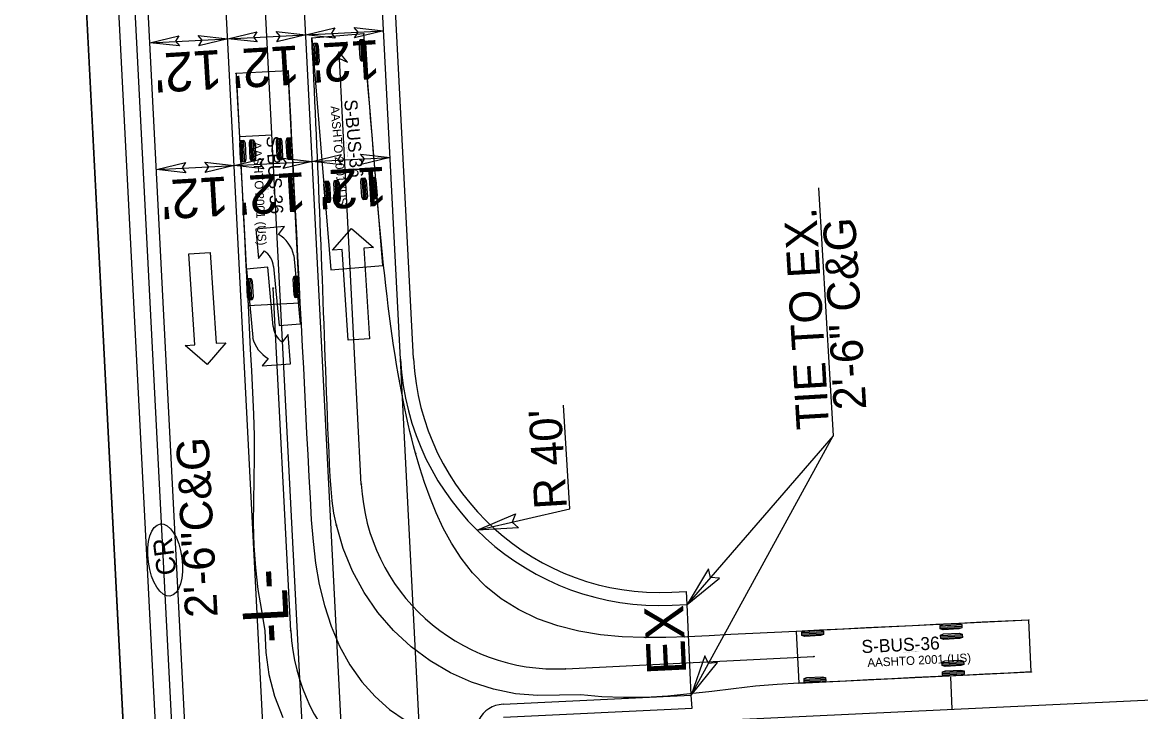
# Model space of a CAD drawing. Extents: x 2367848 to 2369479, y 800728 to 808616.
# Drawn here: x 2368873.3 to 2369045.3, y 802141.1 to 802247.2 of the extents above; entities that cross this region are included whole.
import ezdxf

# ---------------------------------------------------------------- set-up
doc = ezdxf.new("R2010")
doc.units = 0
for name, color, linetype in [('Prop AutoTurn Projected Path', 7, 'Continuous'), ('Prop AutoTurn Simulation', 7, 'Continuous'), ('Prop Conc 2ft 6in Curb and Gutter', 7, 'Continuous'), ('Prop Conc 4in Sidewalk', 7, 'Continuous'), ('Prop Dimension', 7, 'Continuous'), ('Prop EOT', 7, 'Continuous'), ('Prop Horizontal Alignment', 7, 'Continuous'), ('Prop Horizontal Alignment Station Label', 7, 'Continuous'), ('Prop Horizontal Alignment Tick Small', 7, 'Continuous'), ('Prop Lane Arrow CELL', 7, 'Continuous'), ('Prop Lane Lines', 7, 'Continuous'), ('Prop Shade Light', 7, 'Continuous'), ('Prop Terminator CELL', 7, 'Continuous'), ('Prop WCC CELL', 7, 'Continuous'), ('Prop WCR CELL', 7, 'Continuous')]:
    doc.layers.add(name, color=color, linetype=linetype)

# ---------------------------------------------------------------- blocks, each defined once
blk = doc.blocks.new('CR')
at = {"layer": 'Prop WCC CELL'}
blk.add_ellipse((0.02, -0.02), major_axis=(5.61, 0), ratio=0.462467, dxfattribs=at)
blk.add_text('CR', height=3, dxfattribs=at).set_placement((-2.34, -1.5))

msp = doc.modelspace()

# ---------------------------------------------------------------- linework, layer by layer
at = {"layer": 'Prop AutoTurn Projected Path'}
for p, q in [((2368925.4, 802176.14), (2368921.99, 802242.64)), ((2368914.55, 802153.56), (2368911.84, 802206.31)), ((2368956.83, 802147.72), (2368995, 802149.59))]:
    msp.add_line(p, q, dxfattribs=at)
for centre, end in [((2368955.36, 802177.68), 272.8044), ((2368944.51, 802155.1), 272.8888)]:
    msp.add_arc(centre, 30, 182.9405, end, dxfattribs=at)
at = {"layer": 'Prop AutoTurn Simulation'}
for p, q in [((2368925.77, 802245.46), (2368917.8, 802244.8)), ((2368917.8, 802244.8), (2368920.73, 802209.12)), ((2368917.8, 802244.8), (2368917.8, 802244.8)), ((2368925.68, 802244.59), (2368925.85, 802241.26)), ((2368928.71, 802209.78), (2368925.77, 802245.46)), ((2368918.12, 802244.01), (2368918.29, 802240.68)), ((2368918.33, 802244.02), (2368918.5, 802240.69)), ((2368918.54, 802244.03), (2368918.71, 802240.7)), ((2368925.27, 802244.57), (2368925.44, 802241.24)), ((2368925.48, 802244.58), (2368925.65, 802241.25)), ((2368914.13, 802239.77), (2368906.14, 802239.36)), ((2368915.96, 802204.02), (2368914.13, 802239.77)), ((2368906.14, 802239.36), (2368907.97, 802203.61)), ((2368908.54, 802225.8), (2368908.37, 802229.13)), ((2368908.75, 802225.81), (2368908.58, 802229.14)), ((2368908.96, 802225.82), (2368908.79, 802229.15)), ((2368912.7, 802226.02), (2368912.53, 802229.34)), ((2368912.91, 802226.03), (2368912.74, 802229.36)), ((2368913.12, 802226.04), (2368912.95, 802229.37)), ((2368914.2, 802226.09), (2368914.03, 802229.42)), ((2368914.41, 802226.1), (2368914.24, 802229.43)), ((2368914.62, 802226.11), (2368914.45, 802229.44)), ((2368907.04, 802225.72), (2368906.87, 802229.05)), ((2368907.25, 802225.74), (2368907.08, 802229.06)), ((2368907.46, 802225.75), (2368907.29, 802229.08)), ((2368919.82, 802222.76), (2368920.09, 802219.44)), ((2368920.03, 802222.77), (2368920.3, 802219.45)), ((2368920.24, 802222.79), (2368920.51, 802219.47)), ((2368921.32, 802222.88), (2368921.59, 802219.56)), ((2368921.52, 802222.9), (2368921.8, 802219.58)), ((2368921.73, 802222.92), (2368922, 802219.59)), ((2368925.47, 802223.22), (2368925.74, 802219.9)), ((2368925.68, 802223.24), (2368925.95, 802219.92)), ((2368925.88, 802223.26), (2368926.16, 802219.93)), ((2368926.96, 802223.35), (2368927.24, 802220.02)), ((2368927.17, 802223.36), (2368927.44, 802220.04)), ((2368927.38, 802223.38), (2368927.65, 802220.06)), ((2368920.73, 802209.12), (2368928.71, 802209.78)), ((2368908.14, 802204.45), (2368907.97, 802207.78)), ((2368908.35, 802204.46), (2368908.17, 802207.79)), ((2368908.55, 802204.47), (2368908.38, 802207.8)), ((2368915.29, 802204.82), (2368915.12, 802208.15)), ((2368915.5, 802204.83), (2368915.33, 802208.16)), ((2368915.71, 802204.84), (2368915.54, 802208.17)), ((2368907.97, 802203.61), (2368915.96, 802204.02)), ((2368915.96, 802204.02), (2368915.96, 802204.02)), ((2369028.06, 802155.21), (2368992.3, 802153.46)), ((2369028.45, 802147.22), (2369028.06, 802155.21)), ((2368992.3, 802153.46), (2368992.7, 802145.47)), ((2368993.15, 802153.29), (2368996.48, 802153.46)), ((2369014.42, 802154.33), (2369017.75, 802154.5)), ((2369014.43, 802154.13), (2369017.76, 802154.29)), ((2369014.44, 802153.92), (2369017.77, 802154.08)), ((2368993.16, 802153.08), (2368996.49, 802153.25)), ((2368993.17, 802152.88), (2368996.5, 802153.04)), ((2369014.5, 802152.84), (2369017.82, 802153)), ((2369014.51, 802152.63), (2369017.83, 802152.79)), ((2369014.52, 802152.42), (2369017.85, 802152.58)), ((2369014.7, 802148.67), (2369018.03, 802148.84)), ((2369014.71, 802148.47), (2369018.04, 802148.63)), ((2369014.72, 802148.26), (2369018.05, 802148.42)), ((2368992.7, 802145.47), (2369028.45, 802147.22)), ((2369014.77, 802147.18), (2369018.1, 802147.34)), ((2369014.78, 802146.97), (2369018.11, 802147.13)), ((2369014.79, 802146.76), (2369018.12, 802146.92)), ((2368992.7, 802145.47), (2368992.7, 802145.47)), ((2368993.5, 802146.13), (2368996.83, 802146.3)), ((2368993.51, 802145.93), (2368996.84, 802146.09)), ((2368993.52, 802145.72), (2368996.85, 802145.88))]:
    msp.add_line(p, q, dxfattribs=at)
for points in [[(2368921.56, 802169.82), (2368921.19, 802171.67), (2368920.91, 802173.54), (2368920.74, 802175.42), (2368920.63, 802177.31), (2368920.52, 802179.18), (2368920.43, 802181.05), (2368920.34, 802182.9), (2368920.26, 802184.74), (2368920.19, 802186.56), (2368920.12, 802188.38), (2368920.05, 802190.18), (2368919.98, 802191.98), (2368919.92, 802193.76), (2368919.86, 802195.54), (2368919.79, 802197.31), (2368919.73, 802199.07), (2368919.67, 802200.83), (2368919.6, 802202.57), (2368919.54, 802204.32), (2368919.48, 802206.05), (2368919.41, 802207.78), (2368919.35, 802209.51), (2368919.28, 802211.23), (2368919.21, 802212.95), (2368919.14, 802214.66), (2368919.07, 802216.38), (2368919, 802218.08), (2368918.93, 802219.79), (2368918.86, 802221.49), (2368918.79, 802223.19), (2368918.71, 802224.89), (2368918.64, 802226.58), (2368918.56, 802228.28), (2368918.49, 802229.97), (2368918.41, 802231.66), (2368918.33, 802233.35), (2368918.26, 802235.04), (2368918.18, 802236.72), (2368918.1, 802238.41), (2368918.02, 802240.09), (2368917.94, 802241.77), (2368917.86, 802243.45), (2368917.8, 802244.8)], [(2368933.74, 802180.89), (2368933.44, 802182.01), (2368933.15, 802183.12), (2368932.88, 802184.22), (2368932.62, 802185.35), (2368932.35, 802186.54), (2368932.08, 802187.77), (2368931.82, 802189.06), (2368931.56, 802190.38), (2368931.31, 802191.74), (2368931.07, 802193.13), (2368930.83, 802194.55), (2368930.59, 802196), (2368930.37, 802197.47), (2368930.15, 802198.96), (2368929.94, 802200.47), (2368929.74, 802202), (2368929.55, 802203.54), (2368929.36, 802205.09), (2368929.17, 802206.65), (2368929, 802208.23), (2368928.83, 802209.81), (2368928.66, 802211.41), (2368928.5, 802213.01), (2368928.35, 802214.61), (2368928.2, 802216.22), (2368928.05, 802217.84), (2368927.91, 802219.47), (2368927.78, 802221.09), (2368927.64, 802222.72), (2368927.51, 802224.36), (2368927.37, 802225.99), (2368927.24, 802227.63), (2368927.1, 802229.28), (2368926.97, 802230.92), (2368926.83, 802232.57), (2368926.7, 802234.21), (2368926.56, 802235.86), (2368926.42, 802237.51), (2368926.29, 802239.17), (2368926.15, 802240.82), (2368926.02, 802242.47), (2368925.88, 802244.13), (2368925.77, 802245.46)], [(2368914.13, 802239.77), (2368914.31, 802236.2), (2368914.49, 802232.62), (2368914.68, 802229.05), (2368914.86, 802225.47), (2368915.04, 802221.9), (2368915.23, 802218.32), (2368915.41, 802214.75), (2368915.59, 802211.17), (2368915.78, 802207.6), (2368915.96, 802204.02), (2368915.96, 802204.02), (2368916.13, 802200.68), (2368916.3, 802197.34), (2368916.48, 802194), (2368916.65, 802190.66), (2368916.82, 802187.33), (2368916.99, 802183.99), (2368917.16, 802180.65), (2368917.33, 802177.31), (2368917.51, 802173.97), (2368917.7, 802170.63), (2368917.97, 802167.3), (2368918.36, 802163.98), (2368918.93, 802160.69), (2368919.71, 802157.44), (2368920.74, 802154.26), (2368922.05, 802151.19), (2368923.63, 802148.32), (2368925.47, 802145.72), (2368927.52, 802143.42), (2368929.75, 802141.45), (2368932.12, 802139.81)], [(2368906.14, 802239.36), (2368906.32, 802235.79), (2368906.5, 802232.21), (2368906.69, 802228.64), (2368906.87, 802225.06), (2368907.05, 802221.49), (2368907.24, 802217.91), (2368907.42, 802214.34), (2368907.6, 802210.76), (2368907.79, 802207.19), (2368907.97, 802203.61), (2368907.97, 802203.61), (2368907.97, 802203.61), (2368908.14, 802200.27), (2368908.32, 802196.93), (2368908.49, 802193.59), (2368908.66, 802190.25), (2368908.83, 802186.92), (2368908.93, 802183.57), (2368908.93, 802180.22), (2368908.86, 802176.86), (2368908.79, 802173.47), (2368908.78, 802170.07), (2368908.87, 802166.66), (2368909.1, 802163.27), (2368909.5, 802159.92), (2368910.04, 802156.7), (2368910.54, 802153.53), (2368910.72, 802150.19), (2368911.19, 802146.83), (2368912.05, 802143.49), (2368913.31, 802140.22)], [(2369028.06, 802155.21), (2369024.49, 802155.04), (2369020.91, 802154.86), (2369017.33, 802154.69), (2369013.76, 802154.51), (2369010.18, 802154.34), (2369006.61, 802154.16), (2369003.03, 802153.99), (2368999.46, 802153.81), (2368995.88, 802153.63), (2368992.3, 802153.46), (2368992.3, 802153.46), (2368992.3, 802153.46), (2368988.96, 802153.3), (2368985.61, 802153.13), (2368982.26, 802152.97), (2368978.91, 802152.8), (2368975.57, 802152.64), (2368972.22, 802152.53), (2368968.86, 802152.5), (2368965.52, 802152.63), (2368962.18, 802152.94), (2368958.88, 802153.49), (2368955.63, 802154.31), (2368952.5, 802155.42), (2368949.58, 802156.82), (2368946.91, 802158.49), (2368944.54, 802160.38), (2368942.49, 802162.48), (2368940.75, 802164.72), (2368939.27, 802167.04), (2368938.01, 802169.38), (2368936.92, 802171.72), (2368935.97, 802174.05), (2368935.14, 802176.36), (2368934.4, 802178.64), (2368933.74, 802180.89)], [(2369028.45, 802147.22), (2369024.88, 802147.05), (2369021.3, 802146.87), (2369017.73, 802146.7), (2369014.15, 802146.52), (2369010.57, 802146.35), (2369007, 802146.17), (2369003.42, 802145.99), (2368999.85, 802145.82), (2368996.27, 802145.64), (2368992.7, 802145.47), (2368992.7, 802145.47), (2368989.35, 802145.3), (2368986.01, 802145.02), (2368982.66, 802144.64), (2368979.31, 802144.22), (2368975.93, 802143.83), (2368972.53, 802143.51), (2368969.11, 802143.31), (2368965.71, 802143.27), (2368962.37, 802143.4), (2368959.15, 802143.68), (2368955.87, 802143.67), (2368952.52, 802143.58), (2368949.12, 802143.86), (2368945.72, 802144.55), (2368942.36, 802145.63), (2368939.1, 802147.09), (2368935.99, 802148.92), (2368933.06, 802151.1), (2368930.37, 802153.6), (2368927.94, 802156.39), (2368925.82, 802159.45), (2368924.03, 802162.73), (2368922.61, 802166.2), (2368921.56, 802169.82)]]:
    msp.add_lwpolyline(points, dxfattribs=at)
for points in [[(2368925.22, 802244.57), (2368925.74, 802244.59), (2368925.92, 802244.14), (2368926.04, 802241.74), (2368925.91, 802241.27), (2368925.39, 802241.24), (2368925.21, 802241.7), (2368925.08, 802244.09)], [(2368918.07, 802244.01), (2368918.59, 802244.03), (2368918.77, 802243.57), (2368918.89, 802241.18), (2368918.76, 802240.7), (2368918.24, 802240.68), (2368918.06, 802241.13), (2368917.94, 802243.53)], [(2368921.99, 802242.64), (2368920.85, 802240.99), (2368922.04, 802241.64), (2368923.29, 802241.11)], [(2368909.01, 802225.83), (2368908.49, 802225.8), (2368908.31, 802226.26), (2368908.19, 802228.65), (2368908.32, 802229.13), (2368908.84, 802229.15), (2368909.02, 802228.7), (2368909.14, 802226.3)], [(2368913.17, 802226.04), (2368912.65, 802226.01), (2368912.47, 802226.47), (2368912.35, 802228.87), (2368912.48, 802229.34), (2368913, 802229.37), (2368913.18, 802228.91), (2368913.3, 802226.51)], [(2368914.67, 802226.12), (2368914.15, 802226.09), (2368913.97, 802226.55), (2368913.85, 802228.94), (2368913.98, 802229.42), (2368914.5, 802229.45), (2368914.68, 802228.99), (2368914.8, 802226.59)], [(2368907.51, 802225.75), (2368906.99, 802225.72), (2368906.81, 802226.18), (2368906.69, 802228.58), (2368906.82, 802229.05), (2368907.34, 802229.08), (2368907.52, 802228.62), (2368907.64, 802226.22)], [(2368919.77, 802222.75), (2368920.29, 802222.8), (2368920.48, 802222.34), (2368920.68, 802219.95), (2368920.56, 802219.47), (2368920.04, 802219.43), (2368919.85, 802219.88), (2368919.65, 802222.28)], [(2368921.26, 802222.88), (2368921.78, 802222.92), (2368921.98, 802222.47), (2368922.17, 802220.08), (2368922.06, 802219.6), (2368921.54, 802219.55), (2368921.34, 802220.01), (2368921.15, 802222.4)], [(2368925.42, 802223.22), (2368925.93, 802223.26), (2368926.13, 802222.81), (2368926.33, 802220.42), (2368926.21, 802219.94), (2368925.69, 802219.9), (2368925.5, 802220.35), (2368925.3, 802222.74)], [(2368926.91, 802223.34), (2368927.43, 802223.38), (2368927.62, 802222.93), (2368927.82, 802220.54), (2368927.7, 802220.06), (2368927.19, 802220.02), (2368926.99, 802220.47), (2368926.79, 802222.86)], [(2368908.61, 802204.48), (2368908.09, 802204.45), (2368907.91, 802204.91), (2368907.78, 802207.3), (2368907.91, 802207.78), (2368908.43, 802207.81), (2368908.61, 802207.35), (2368908.74, 802204.95)], [(2368915.76, 802204.84), (2368915.24, 802204.82), (2368915.06, 802205.28), (2368914.94, 802207.67), (2368915.07, 802208.15), (2368915.59, 802208.17), (2368915.77, 802207.72), (2368915.89, 802205.32)], [(2368993.17, 802152.82), (2368993.14, 802153.34), (2368993.6, 802153.52), (2368996, 802153.64), (2368996.47, 802153.51), (2368996.5, 802152.99), (2368996.04, 802152.81), (2368993.64, 802152.69)], [(2369014.44, 802153.87), (2369014.42, 802154.39), (2369014.88, 802154.57), (2369017.28, 802154.68), (2369017.75, 802154.55), (2369017.77, 802154.03), (2369017.32, 802153.85), (2369014.92, 802153.73)], [(2369014.52, 802152.37), (2369014.49, 802152.89), (2369014.95, 802153.07), (2369017.35, 802153.18), (2369017.82, 802153.05), (2369017.85, 802152.53), (2369017.39, 802152.35), (2369014.99, 802152.23)], [(2369014.72, 802148.21), (2369014.7, 802148.73), (2369015.16, 802148.91), (2369017.55, 802149.02), (2369018.03, 802148.89), (2369018.05, 802148.37), (2369017.59, 802148.19), (2369015.2, 802148.07)], [(2369014.8, 802146.71), (2369014.77, 802147.23), (2369015.23, 802147.41), (2369017.63, 802147.52), (2369018.1, 802147.39), (2369018.12, 802146.87), (2369017.67, 802146.69), (2369015.27, 802146.58)], [(2368993.52, 802145.67), (2368993.5, 802146.19), (2368993.95, 802146.37), (2368996.35, 802146.48), (2368996.82, 802146.35), (2368996.85, 802145.83), (2368996.39, 802145.65), (2368993.99, 802145.53)]]:
    msp.add_lwpolyline(points, close=True, dxfattribs=at)
for centre in [(2368917.8, 802244.8), (2368925.77, 802245.46), (2368921.99, 802242.64), (2368914.13, 802239.77), (2368906.14, 802239.36), (2368911.84, 802206.31), (2368933.74, 802180.89), (2368933.74, 802180.89), (2368925.4, 802176.14), (2368925.4, 802176.14), (2368921.56, 802169.82), (2368921.56, 802169.82), (2369028.06, 802155.21), (2368914.55, 802153.56), (2368914.55, 802153.56), (2368995, 802149.59), (2368956.83, 802147.72), (2368956.83, 802147.72), (2369028.45, 802147.22)]:
    msp.add_circle(centre, 0.0417, dxfattribs=at)
at = {"layer": 'Prop Conc 2ft 6in Curb and Gutter'}
for p, q in [((2368933.42, 802195.49), (2368920.7, 802443.16)), ((2368900.11, 802064.22), (2368880.75, 802441.11)), ((2368973.14, 802159.48), (2368975.4, 802159.59)), ((2368975.5, 802157.59), (2368975.4, 802159.59)), ((2368976.27, 802141.66), (2368976.15, 802143.66)), ((2368947.29, 802140.24), (2368976.27, 802141.66))]:
    msp.add_line(p, q, dxfattribs=at)
msp.add_arc((2368971.37, 802197.44), 38, 182.9405, 272.6684, dxfattribs=at)
at = {"layer": 'Prop Conc 4in Sidewalk'}
for p, q in [((2368892.58, 802064.58), (2368873.26, 802440.72)), ((2368897.6, 802064.34), (2368878.26, 802440.98))]:
    msp.add_line(p, q, dxfattribs=at)
at = {"layer": 'Prop Dimension'}
for p, q in [((2368892.88, 802244.08), (2368928.83, 802245.93)), ((2368893.88, 802224.58), (2368929.83, 802226.42)), ((2368995.73, 802221.72), (2368997.96, 802183.58)), ((2368957.45, 802172.32), (2368956.49, 802188.29)), ((2368997.96, 802183.58), (2368975.5, 802157.59)), ((2368976.15, 802143.66), (2368997.96, 802183.58)), ((2368943.21, 802169.03), (2368957.45, 802172.32))]:
    msp.add_line(p, q, dxfattribs=at)
at = {"layer": 'Prop EOT'}
for p, q in [((2368931.42, 802195.39), (2368918.7, 802443.06)), ((2368902.12, 802064.13), (2368882.75, 802441.21)), ((2368973.23, 802157.48), (2368975.5, 802157.59)), ((2368976.15, 802143.66), (2368975.5, 802157.59)), ((2368947.2, 802142.24), (2368976.15, 802143.66))]:
    msp.add_line(p, q, dxfattribs=at)
for centre, radius, start, end in [((2368971.37, 802197.44), 40, 182.9405, 272.6684), ((2368947.4, 802137.81), 4.44, 92.4729, 272.8864)]:
    msp.add_arc(centre, radius, start, end, dxfattribs=at)
at = {"layer": 'Prop Horizontal Alignment'}
for p, q in [((2368929.17, 801888.4), (2368900.73, 802442.14)), ((2368916.41, 802136.78), (2369182.45, 802149.35))]:
    msp.add_line(p, q, dxfattribs=at)
at = {"layer": 'Prop Horizontal Alignment Tick Small'}
for p, q in [((2368911.63, 802229.83), (2368906.64, 802229.58)), ((2368911.63, 802229.83), (2368906.64, 802229.58)), ((2369016.3, 802141.5), (2369016.06, 802146.49))]:
    msp.add_line(p, q, dxfattribs=at)
at = {"layer": 'Prop Lane Arrow CELL'}
for p, q in [((2368913.59, 802215.77), (2368909.16, 802215.37)), ((2368909.16, 802215.37), (2368909.57, 802210.88)), ((2368912.65, 802214.58), (2368913.59, 802215.77)), ((2368920.98, 802212.16), (2368923.87, 802215.51)), ((2368923.87, 802215.51), (2368927.26, 802212.57)), ((2368909.57, 802210.88), (2368910.52, 802212.03)), ((2368922.47, 802212.26), (2368920.98, 802212.16)), ((2368923.38, 802198.29), (2368922.47, 802212.26)), ((2368927.26, 802212.57), (2368925.77, 802212.48)), ((2368925.77, 802212.48), (2368926.68, 802198.5)), ((2368898.87, 802211.57), (2368902.17, 802211.78)), ((2368899.78, 802197.6), (2368898.87, 802211.57)), ((2368902.17, 802211.78), (2368903.08, 802197.81)), ((2368916.02, 802200.83), (2368915.05, 802211.34)), ((2368911.01, 802209.51), (2368907.72, 802209.21)), ((2368907.72, 802209.21), (2368908.69, 802198.7)), ((2368911.84, 802200.4), (2368911.01, 802209.51)), ((2368911.9, 802209.64), (2368912.74, 802200.53)), ((2368912.74, 802200.53), (2368916.02, 802200.83)), ((2368914.17, 802199.16), (2368913.22, 802198.01)), ((2368914.53, 802194.67), (2368914.17, 802199.16)), ((2368926.68, 802198.5), (2368923.38, 802198.29)), ((2368898.29, 802197.5), (2368899.78, 802197.6)), ((2368901.68, 802194.56), (2368898.29, 802197.5)), ((2368904.57, 802197.91), (2368901.68, 802194.56)), ((2368903.08, 802197.81), (2368904.57, 802197.91)), ((2368911.09, 802195.46), (2368910.14, 802194.32)), ((2368910.14, 802194.32), (2368914.53, 802194.67))]:
    msp.add_line(p, q, dxfattribs=at)
for centre, radius, start, end in [((2368909.94, 802210.09), 5.25, 13.9351, 59.2468), ((2368908.62, 802209.36), 3.27, 5.259, 54.9172), ((2368915.09, 802200.69), 3.27, 185.259, 234.9172), ((2368913.77, 802199.96), 5.25, 193.9351, 239.2468)]:
    msp.add_arc(centre, radius, start, end, dxfattribs=at)
at = {"layer": 'Prop Lane Lines'}
for p, q in [((2368933.53, 801920.55), (2368906.72, 802442.44)), ((2368921.54, 801919.93), (2368894.73, 802441.83)), ((2368937.38, 802079.52), (2368931.42, 802195.39))]:
    msp.add_line(p, q, dxfattribs=at)
at = {"layer": 'Prop Shade Light'}
for p, q in [((2368873.26, 802440.72), (2368892.58, 802064.58)), ((2368897.6, 802064.34), (2368878.26, 802440.98))]:
    msp.add_line(p, q, dxfattribs=at)
at = {"layer": 'Prop Terminator CELL'}
for points in [[(2368921.38, 802244.81), (2368916.84, 802245.31), (2368921.31, 802246.39), (2368920.79, 802245.55)], [(2368924.29, 802246.43), (2368928.83, 802245.93), (2368924.36, 802244.86), (2368924.89, 802245.69)], [(2368897.41, 802243.58), (2368892.88, 802244.08), (2368897.34, 802245.15), (2368896.82, 802244.32)], [(2368900.32, 802245.2), (2368904.86, 802244.7), (2368900.39, 802243.63), (2368900.92, 802244.46)], [(2368909.4, 802244.2), (2368904.86, 802244.7), (2368909.33, 802245.77), (2368908.8, 802244.94)], [(2368912.31, 802245.82), (2368916.84, 802245.31), (2368912.38, 802244.24), (2368912.9, 802245.08)], [(2368901.32, 802225.7), (2368905.86, 802225.19), (2368901.39, 802224.12), (2368901.92, 802224.96)], [(2368910.4, 802224.69), (2368905.86, 802225.19), (2368910.33, 802226.26), (2368909.8, 802225.43)], [(2368913.31, 802226.31), (2368917.85, 802225.81), (2368913.38, 802224.74), (2368913.9, 802225.57)], [(2368922.38, 802225.31), (2368917.85, 802225.81), (2368922.31, 802226.88), (2368921.79, 802226.05)], [(2368925.29, 802226.93), (2368929.83, 802226.42), (2368925.36, 802225.35), (2368925.89, 802226.19)], [(2368898.42, 802224.08), (2368893.88, 802224.58), (2368898.35, 802225.65), (2368897.82, 802224.82)], [(2368949.6, 802169.39), (2368943.21, 802169.03), (2368949.13, 802171.55), (2368948.6, 802170.27)], [(2368978.79, 802163.07), (2368975.5, 802157.59), (2368980.48, 802161.65), (2368979.11, 802161.77)], [(2368978.22, 802149.71), (2368976.15, 802143.66), (2368980.17, 802148.68), (2368978.8, 802148.51)]]:
    msp.add_lwpolyline(points, close=True, dxfattribs=at)

# ---------------------------------------------------------------- block references
at = {"layer": 'Prop WCR CELL', "rotation": 97.5424116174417}
msp.add_blockref('CR', (2368895.21, 802164.44), dxfattribs=at)

# ---------------------------------------------------------------- texts
at = {"layer": 'Prop AutoTurn Simulation'}
for s, height, rotation, p in [('AASHTO 2001 (US)', 1.3333, 274.7067, (2368920.66, 802234.31)), ('S-BUS-36', 2, 274.7067, (2368922.76, 802235.27)), ('S-BUS-36', 2, 272.9405, (2368910.8, 802229.69)), ('AASHTO 2001 (US)', 1.3333, 272.9405, (2368908.67, 802228.79)), ('(c) 2014 Transoft Solutions, Inc. All rights reserved.', 0.08, 274.7067, (2368923.08, 802228.91)), ('(c) 2014 Transoft Solutions, Inc. All rights reserved.', 0.08, 272.9405, (2368910.92, 802223.32)), ('S-BUS-36', 2, 2.8044, (2369002.38, 802150.11)), ('AASHTO 2001 (US)', 1.3333, 2.8044, (2369003.27, 802147.98)), ('(c) 2014 Transoft Solutions, Inc. All rights reserved.', 0.08, 2.8044, (2369008.75, 802150.22))]:
    msp.add_text(s, height=height, rotation=rotation, dxfattribs=at).set_placement(p)
at = {"layer": 'Prop Dimension'}
for s, height, rotation, p in [("12'", 6, 183.4586, (2368903.83, 802243)), ("12'", 6, 183.4586, (2368915.78, 802243.67)), ("12'", 6, 183.4586, (2368928.16, 802244.53)), ("12'", 6, 183.4586, (2368916.78, 802224.16)), ("12'", 6, 183.4586, (2368929.16, 802225.02)), ("12'", 6, 183.4586, (2368904.84, 802223.5)), ('TIE TO EX. ', 5, 93.3475, (2368997.36, 802184.68)), ('2\'-6" C&G', 5, 93.3475, (2369003.08, 802187.69)), ("R 40'", 5, 93.4586, (2368957.03, 802172.44)), ('2\'-6"C&G', 5, 92.9405, (2368903.31, 802155.71)), ('EX', 6, 92.7051, (2368975.39, 802146.94))]:
    msp.add_text(s, height=height, rotation=rotation, dxfattribs=at).set_placement(p)
at = {"layer": 'Prop Horizontal Alignment Station Label'}
msp.add_text('-L-', height=7, rotation=92.9405, dxfattribs=at).set_placement((2368914.39, 802151.81))

doc.saveas('drawing.dxf')
